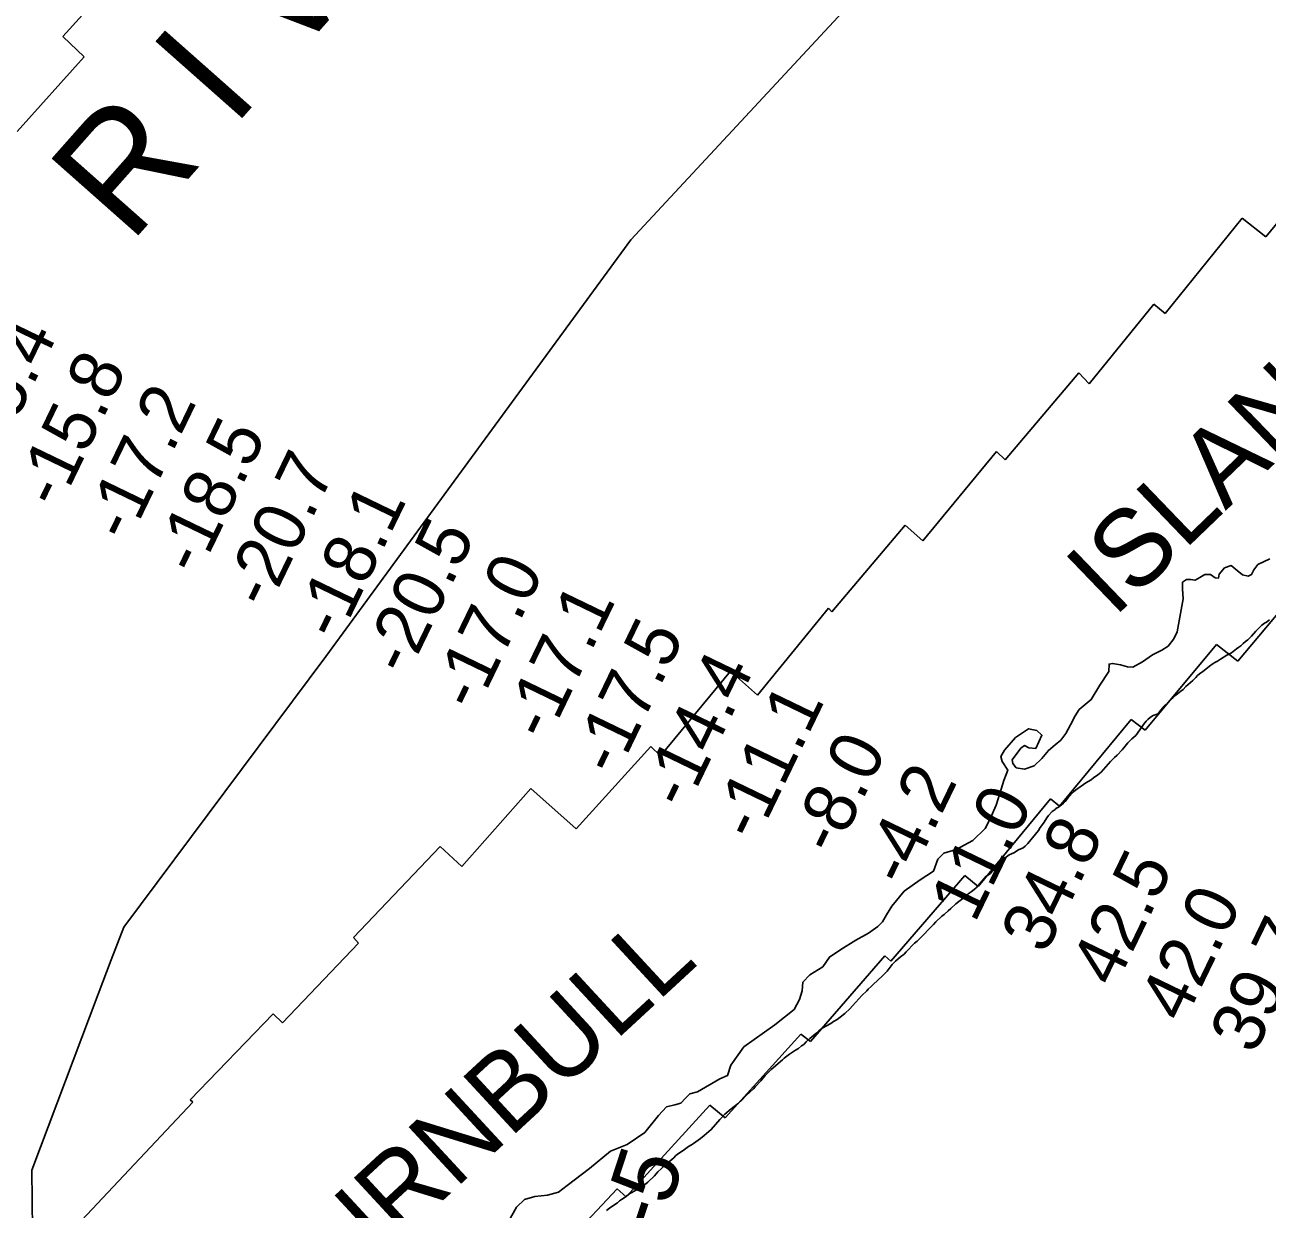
# Model space of a CAD drawing. Extents: x 3146026 to 3183936, y 897894 to 923344.
# Drawn here: x 3151343 to 3152950, y 917237 to 918770 of the extents above; entities that cross this region are included whole.
import ezdxf

# ---------------------------------------------------------------- set-up
doc = ezdxf.new("R2010")
doc.units = 0
for name, color, linetype in [('V-RIVR-EDGE', 7, 'Continuous'), ('V-RIVR-IDEN', 7, 'Continuous'), ('V-RIVR-RANG', 7, 'Continuous'), ('V-RIVR-RANG-IDEN', 7, 'Continuous'), ('V-RRAP-RVMT', 7, 'Continuous'), ('V-RRAP-RVMT-IDEN', 7, 'Continuous'), ('V-SITE-VEGE', 7, 'Continuous'), ('V-TOPO-BNDY', 7, 'Continuous')]:
    doc.layers.add(name, color=color, linetype=linetype)

msp = doc.modelspace()

# ---------------------------------------------------------------- linework, layer by layer
at = {"layer": 'V-RIVR-EDGE'}
for points in [[(3152883.1, 918054.3), (3152887.1, 918053.7), (3152888, 918059.2), (3152895.1, 918067.4), (3152903.9, 918070.1), (3152911.5, 918064), (3152918.2, 918058.2), (3152925.8, 918056.7), (3152930.1, 918058.5), (3152933.1, 918064.6), (3152938.3, 918071.6), (3152953.9, 918079.1)], [(3151968.3, 917221.2), (3151978.7, 917240), (3151989.4, 917249.5), (3152002.5, 917253.7), (3152019, 917255.2), (3152033.3, 917259.1), (3152044.6, 917267.9), (3152073.3, 917289.8), (3152100.4, 917312.2), (3152122.1, 917320.7), (3152144.9, 917336.5), (3152162.4, 917358.4), (3152173, 917369.6), (3152183.7, 917372.3), (3152191.3, 917374.4), (3152197.7, 917380.8), (3152203.2, 917386.3), (3152213, 917389), (3152242, 917406), (3152252, 917410.2), (3152256, 917423.6), (3152273.1, 917447.3), (3152313.1, 917475.9), (3152338.1, 917495.6), (3152345.2, 917508.4), (3152348.5, 917519.6), (3152349.5, 917531.2), (3152358.6, 917540.3), (3152375.4, 917550.9), (3152383.7, 917563.4), (3152398.6, 917573.1), (3152417.8, 917585.5), (3152434.3, 917594.6), (3152446.5, 917603.1), (3152452.3, 917609.2), (3152457.8, 917618.3), (3152464.5, 917629.3), (3152480.7, 917648.7), (3152501.2, 917663.6), (3152518.3, 917674.5), (3152524.1, 917690.4), (3152531.7, 917698), (3152547.9, 917702.8), (3152569.2, 917714.3), (3152585.4, 917730.1), (3152591.5, 917741.4), (3152599.5, 917759.9), (3152606.2, 917780.6), (3152609.6, 917792.2), (3152614.5, 917805.6), (3152607.2, 917816.8), (3152605.7, 917822.9), (3152610.3, 917831.5), (3152624.4, 917847.6), (3152641.5, 917859.1), (3152652.1, 917856.9), (3152658.8, 917850.5), (3152650.8, 917833.5), (3152641.7, 917834.1), (3152636.2, 917837.2), (3152631.3, 917833.8), (3152620.3, 917818.6), (3152621.2, 917814.1), (3152625.5, 917808.3), (3152636.4, 917806.7), (3152648.9, 917811), (3152658.7, 917820.7), (3152667.3, 917831), (3152675.8, 917838), (3152683.1, 917844.4), (3152689.9, 917852.9), (3152695.7, 917864.1), (3152701.8, 917875.7), (3152707, 917883.9), (3152722.6, 917896.7), (3152733.9, 917915.5), (3152745.2, 917933.2), (3152745.8, 917942.6), (3152750.1, 917943.5), (3152760.4, 917941.9), (3152769.6, 917939.2), (3152776.6, 917938.9), (3152789.1, 917945.8), (3152801.9, 917954.6), (3152814.1, 917960.7), (3152822, 917965.9), (3152829.7, 917975.6), (3152833.6, 917984.4), (3152841.4, 918027), (3152840.8, 918040.1), (3152840.8, 918048.6), (3152845.7, 918052.3), (3152851.2, 918052.3), (3152856.9, 918051.3), (3152863, 918054.7), (3152869.8, 918058.6), (3152876.8, 918058.6), (3152883.1, 918054.3)]]:
    msp.add_lwpolyline(points, dxfattribs=at)
at = {"layer": 'V-RRAP-RVMT'}
for p, q in [((3151480.6, 918853.3), (3151391.8, 918754.8)), ((3151391.8, 918754.8), (3151419.5, 918728.5)), ((3151419.5, 918728.5), (3151332.7, 918631.9)), ((3152948.7, 918495.7), (3153041.8, 918609.3)), ((3152818.3, 918396.6), (3152918.1, 918520)), ((3152918.1, 918520), (3152948.7, 918495.7)), ((3152720.1, 918305.4), (3152803.8, 918408.4)), ((3152803.8, 918408.4), (3152818.3, 918396.6)), ((3152611.3, 918207.1), (3152706.4, 918319.5)), ((3152706.4, 918319.5), (3152720.1, 918305.4)), ((3152504.5, 918102.1), (3152600, 918217.7)), ((3152600, 918217.7), (3152611.3, 918207.1)), ((3152387.1, 918010.5), (3152481.8, 918122.5)), ((3152481.8, 918122.5), (3152504.5, 918102.1)), ((3153007.5, 918060.4), (3152912.2, 917946.4)), ((3152290.8, 917902.4), (3152382.4, 918015.2)), ((3152382.4, 918015.2), (3152387.1, 918010.5)), ((3152884.7, 917968), (3152792.3, 917857.2)), ((3152912.2, 917946.4), (3152884.7, 917968)), ((3152165.2, 917823.8), (3152255.9, 917933.4)), ((3152255.9, 917933.4), (3152290.8, 917902.4)), ((3152774.2, 917871.1), (3152681.7, 917758.9)), ((3152792.3, 917857.2), (3152774.2, 917871.1)), ((3152056, 917729.4), (3152152.6, 917835.9)), ((3152152.6, 917835.9), (3152165.2, 917823.8)), ((3151908, 917680.9), (3151997.5, 917781.6)), ((3151997.5, 917781.6), (3152056, 917729.4)), ((3152669.7, 917768.2), (3152576.4, 917654.8)), ((3152681.7, 917758.9), (3152669.7, 917768.2)), ((3151767.8, 917588.9), (3151880.1, 917706.8)), ((3151880.1, 917706.8), (3151908, 917680.9)), ((3152559.2, 917669.1), (3152463.4, 917558)), ((3152576.4, 917654.8), (3152559.2, 917669.1)), ((3151676.2, 917478.5), (3151774.5, 917581.5)), ((3151774.5, 917581.5), (3151767.8, 917588.9)), ((3152455.6, 917564.9), (3152359.1, 917454.3)), ((3152463.4, 917558), (3152455.6, 917564.9)), ((3151556.7, 917378.8), (3151664.1, 917489.9)), ((3151664.1, 917489.9), (3151676.2, 917478.5)), ((3152346.7, 917463.7), (3152248.7, 917355.3)), ((3152359.1, 917454.3), (3152346.7, 917463.7)), ((3151364, 917167.5), (3151559.8, 917375.7)), ((3151559.8, 917375.7), (3151556.7, 917378.8)), ((3152229.2, 917371.6), (3152120.6, 917253.3)), ((3152248.7, 917355.3), (3152229.2, 917371.6)), ((3152109.3, 917263.6), (3152008.7, 917157.3)), ((3152120.6, 917253.3), (3152109.3, 917263.6))]:
    msp.add_line(p, q, dxfattribs=at)
at = {"layer": 'V-SITE-VEGE'}
for points in [[(3152672.2, 917751.9), (3152676.1, 917754.6), (3152676.8, 917755.6), (3152680.2, 917757.6), (3152684.3, 917760.5), (3152686.8, 917762.7), (3152689, 917764.9), (3152693.1, 917770.5), (3152699.6, 917777.3), (3152702.3, 917779.5), (3152715.4, 917789), (3152722.4, 917793.1), (3152725.6, 917795.6), (3152731.2, 917799.5), (3152735.3, 917802.9), (3152747.7, 917816.6), (3152752.8, 917821.7), (3152756.2, 917824.8), (3152762.7, 917831.9), (3152764.9, 917834.3), (3152769.8, 917840.7), (3152775.1, 917846), (3152780.2, 917850.2), (3152782.6, 917853.1), (3152790.4, 917864.3), (3152793.8, 917868.7), (3152795.9, 917871.1), (3152799.1, 917873.8), (3152802.7, 917876), (3152807.8, 917878), (3152810.5, 917880.6), (3152817.1, 917888.2), (3152819.7, 917890.6), (3152822.4, 917893.6), (3152827.3, 917898.2), (3152829.4, 917900.6), (3152831.9, 917902.6), (3152838.7, 917907.5), (3152841.6, 917909.9), (3152845.2, 917913.6), (3152853.9, 917921.4), (3152857.8, 917925.3), (3152860, 917927.9), (3152862.7, 917930.1), (3152867, 917933.1), (3152870.9, 917936), (3152875.8, 917940.1), (3152880.4, 917943.5), (3152883.3, 917945.3), (3152886.2, 917946.5), (3152890.1, 917949.2), (3152898.1, 917954.3), (3152904.2, 917957.2), (3152910.8, 917962.6), (3152913.7, 917964.8), (3152916.3, 917966.5), (3152919.2, 917969.4), (3152922.4, 917971.9), (3152925.1, 917974.3), (3152927.5, 917976.2), (3152929.9, 917978.7), (3152935.5, 917985.3), (3152941.1, 917990.9), (3152943.5, 917993), (3152946.7, 917995.5), (3152949.6, 917997), (3152953.2, 917999.9)], [(3152146.4, 917270.2), (3152148.8, 917272.2), (3152157.5, 917280.5), (3152161.7, 917285.6), (3152166.3, 917289.7), (3152169.4, 917292.9), (3152171.9, 917295.1), (3152182.3, 917303.6), (3152185.2, 917306.6), (3152188.6, 917309.2), (3152194.4, 917313.1), (3152201.5, 917318.3), (3152205.4, 917320.5), (3152207.8, 917322.4), (3152216.8, 917328.8), (3152221.6, 917332.4), (3152230.8, 917340.2), (3152241.8, 917353.4), (3152248.3, 917360), (3152256.8, 917367), (3152266.3, 917374.3), (3152270.1, 917378), (3152276.2, 917384.3), (3152285.4, 917393.1), (3152287.6, 917395.6), (3152295.1, 917403.1), (3152300.7, 917410.2), (3152308.5, 917418), (3152323, 917430.4), (3152325.2, 917432.6), (3152332.3, 917438), (3152337.1, 917441.4), (3152339.8, 917443.1), (3152343.9, 917445.3), (3152347.6, 917448.5), (3152350.5, 917450.4), (3152353.9, 917453.6), (3152358.5, 917458.2), (3152366, 917464.5), (3152369.9, 917468.2), (3152374.2, 917471.4), (3152385.7, 917477.7), (3152389.1, 917479.9), (3152393.7, 917482.6), (3152397.6, 917485.5), (3152403.6, 917490.6), (3152410.4, 917496.7), (3152413.8, 917500.4), (3152417.9, 917505.3), (3152425.9, 917513.8), (3152432, 917519.7), (3152434, 917522.1), (3152437.6, 917525.3), (3152440.3, 917528.2), (3152452.4, 917539.2), (3152458.7, 917545.2), (3152465.2, 917553.8), (3152469.4, 917558.2), (3152475.7, 917563.8), (3152480.5, 917567.4), (3152483.2, 917570.3), (3152494.1, 917581.3), (3152497.5, 917584.2), (3152505.5, 917592.3), (3152512.3, 917599.6), (3152518.6, 917605.7), (3152521.3, 917608.9), (3152529.3, 917616.4), (3152532.2, 917618.6), (3152537.3, 917623.5), (3152540.9, 917626.4), (3152547.5, 917632.5), (3152551.1, 917635.4), (3152556.5, 917639.3), (3152560.6, 917642.7), (3152563.3, 917645.2), (3152567.2, 917647.9), (3152573.2, 917652.5), (3152576.4, 917656.2), (3152578.8, 917659.3), (3152586.8, 917668.1), (3152589.7, 917669.8), (3152592.4, 917671.8), (3152594.6, 917674.7), (3152596.5, 917678.1), (3152598.9, 917681), (3152605.5, 917687.8), (3152616.4, 917695.9), (3152619.3, 917697.3), (3152622.5, 917698.6), (3152628.3, 917702.2), (3152634.4, 917704.9), (3152637.1, 917706.9), (3152640.4, 917710.5), (3152654.3, 917727.3), (3152656.7, 917731), (3152659.6, 917734.9), (3152661.5, 917738.3), (3152665.2, 917743.7), (3152667.4, 917746.6), (3152672.2, 917751.9)], [(3152095.2, 917235.6), (3152099.3, 917238.3), (3152106.1, 917243.4), (3152109.5, 917245.6), (3152112.1, 917247.8), (3152114.8, 917249.5), (3152118, 917251.9), (3152121.6, 917254.4), (3152125.5, 917257.3), (3152128.2, 917258.8), (3152131.1, 917260.7), (3152139.8, 917265.8), (3152146.4, 917270.2)]]:
    msp.add_lwpolyline(points, dxfattribs=at)
at = {"layer": 'V-TOPO-BNDY'}
msp.add_lwpolyline([(3151352.6, 917210), (3151351.8, 917287.8), (3151437.6, 917515.3), (3151454.3, 917560), (3151470.7, 917602.4), (3151731.9, 917952.4), (3152126.9, 918492), (3152508.8, 918903.5), (3152818, 919233.7), (3152842.7, 919259.6), (3153265.7, 919700), (3153697.1, 920260.1), (3153745.3, 920322.8), (3153843.6, 920396.5), (3154495.8, 920886), (3154603.3, 920966.4), (3154757.1, 921061.6), (3155165.9, 921315.5), (3155302.7, 921422.4), (3155461.9, 921546.6)], dxfattribs=at)

# ---------------------------------------------------------------- texts
at = {"layer": 'V-RIVR-IDEN'}
msp.add_text('R I V E R', height=150, rotation=48.4686, dxfattribs=at).set_placement((3151478.6, 918485.3))
at = {"layer": 'V-RIVR-RANG'}
for s, p in [('-15.4', (3151296.4, 918184.7)), ('-15.8', (3151386.6, 918141.4)), ('-17.2', (3151476.7, 918098.2)), ('-18.5', (3151566.9, 918054.9)), ('-20.7', (3151657, 918011.6)), ('-18.1', (3151748.2, 917970.5)), ('-20.5', (3151837.3, 917925.1)), ('-17.0', (3151926.2, 917879.2)), ('-17.1', (3152018.7, 917840.7)), ('-17.5', (3152107.8, 917795.3)), ('-14.4', (3152198, 917752)), ('-11.1', (3152289.1, 917710.9)), ('-8.0', (3152391.5, 917692.8)), ('-4.2', (3152482.9, 917652.1)), ('11.0', (3152571.8, 917606.2)), ('34.8', (3152663.2, 917565.6)), ('42.5', (3152753.3, 917522.3)), ('42.0', (3152842.2, 917476.4)), ('39.7', (3152933.6, 917435.8))]:
    msp.add_text(s, height=67, rotation=64.2183, dxfattribs=at).set_placement(p)
at = {"layer": 'V-RIVR-RANG-IDEN'}
msp.add_text('R-5', height=83, rotation=71.8858, dxfattribs=at).set_placement((3152140.6, 917128.5))
at = {"layer": 'V-RRAP-RVMT-IDEN'}
for s, rotation, p in [('ISLAND', 43.9004, (3152751.7, 918001.6)), ('TURNBULL', 42.7542, (3151697.3, 917076))]:
    msp.add_text(s, height=100, rotation=rotation, dxfattribs=at).set_placement(p)

doc.saveas('drawing.dxf')
